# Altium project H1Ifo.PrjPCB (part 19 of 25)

## Sheet IfoEndX3.SchDoc: D1800185
size C; Engineer: Daniel Sigg; DocumentNumber: 7; Revision: 4; SheetNumber: 7; SheetTotal: 8
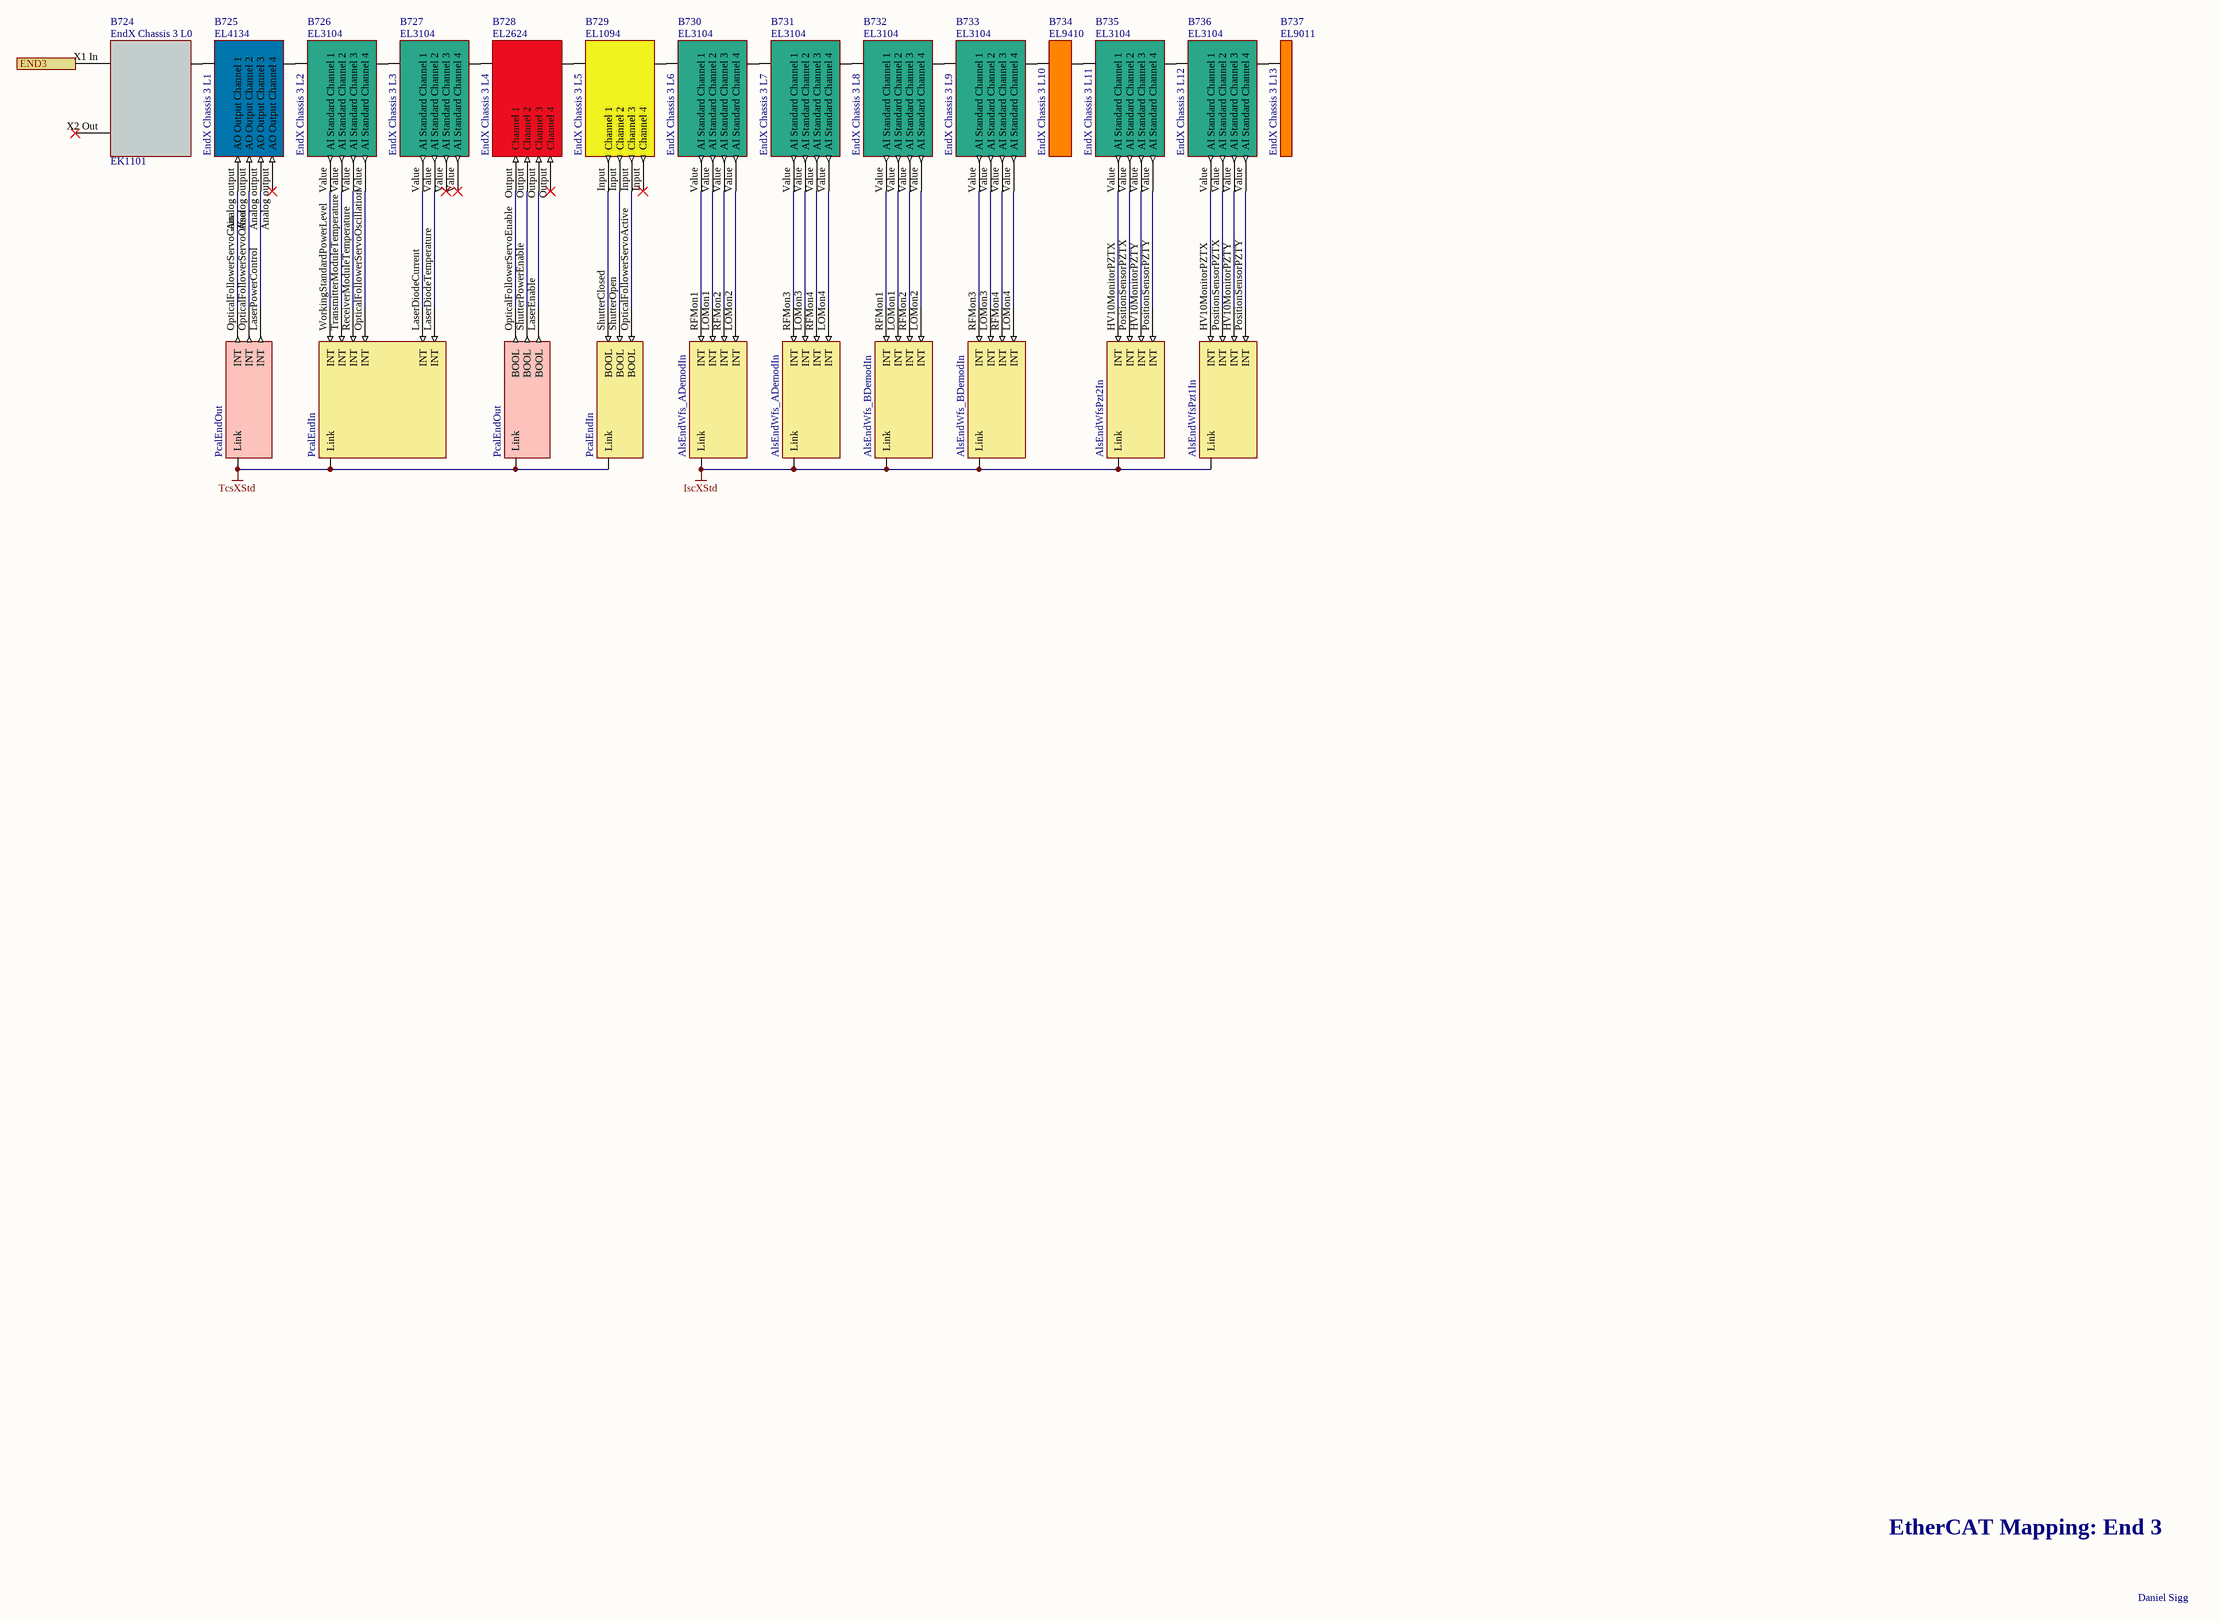
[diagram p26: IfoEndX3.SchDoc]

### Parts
B724  EndX Chassis 3 L0  Part Number: EK1101
B725  EndX Chassis 3 L1  Part Number: EL4134  (mechanical)
B726  EndX Chassis 3 L2  Part Number: EL3104  (mechanical)
B727  EndX Chassis 3 L3  Part Number: EL3104  (mechanical)
B728  EndX Chassis 3 L4  Part Number: EL2624  (mechanical)
B729  EndX Chassis 3 L5  Part Number: EL1094  (mechanical)
B730  EndX Chassis 3 L6  Part Number: EL3104  (mechanical)
B731  EndX Chassis 3 L7  Part Number: EL3104  (mechanical)
B732  EndX Chassis 3 L8  Part Number: EL3104  (mechanical)
B733  EndX Chassis 3 L9  Part Number: EL3104  (mechanical)
B734  EndX Chassis 3 L10  Part Number: EL9410  (mechanical)
B735  EndX Chassis 3 L11  Part Number: EL3104  (mechanical)
B736  EndX Chassis 3 L12  Part Number: EL3104  (mechanical)
B737  EndX Chassis 3 L13  Part Number: EL9011  (mechanical)
V584  PcalEndOut  (parts A,B of 2)  (no BOM)
V585  PcalEndIn  (parts A,B of 2)  (no BOM)
V586  AlsEndWfs_ADemodIn  (parts A,B of 2)  (no BOM)
V594  AlsEndWfs_BDemodIn  (parts A,B of 2)  (no BOM)
V595  AlsEndWfsPzt2In  (no BOM)
V596  AlsEndWfsPzt1In  (no BOM)

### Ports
END3

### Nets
IscXStd: V586.0(Link) V586.1(Link) V594.0(Link) V594.1(Link) V595.0(Link) V596.0(Link)
TcsXStd: V584.0(Link) V584.1(Link) V585.0(Link) V585.1(Link)
NetB710_X2 Out: B724.X1_In(A) ; port END3
NetB724_Ebus: B724.Ebus(B) B725.Ebus(A)
NetB725_Analog output: B725.Analog_output(AO_Output_Channel_1) V584.OpticalFollowerServoGain(INT)
NetB725_Analog output: B725.Analog_output(AO_Output_Channel_2) V584.OpticalFollowerServoOffset(INT)  [a separate net that carries the same name]
NetB725_Analog output: B725.Analog_output(AO_Output_Channel_3) V584.LaserPowerControl(INT)  [a separate net that carries the same name]
NetB725_Ebus: B725.Ebus(B) B726.Ebus(A)
NetB726_Ebus: B726.Ebus(B) B727.Ebus(A)
NetB726_Value: B726.Value(AI_Standard_Channel_1) V585.WorkingStandardPowerLevel(INT)
NetB726_Value: B726.Value(AI_Standard_Channel_2) V585.TransmitterModuleTemperature(INT)  [a separate net that carries the same name]
NetB726_Value: B726.Value(AI_Standard_Channel_3) V585.ReceiverModuleTemperature(INT)  [a separate net that carries the same name]
NetB726_Value: B726.Value(AI_Standard_Channel_4) V585.OpticalFollowerServoOscillation(INT)  [a separate net that carries the same name]
NetB727_Ebus: B727.Ebus(B) B728.Ebus(A)
NetB727_Value: B727.Value(AI_Standard_Channel_1) V585.LaserDiodeCurrent(INT)
NetB727_Value: B727.Value(AI_Standard_Channel_2) V585.LaserDiodeTemperature(INT)  [a separate net that carries the same name]
NetB728_Ebus: B728.Ebus(B) B729.Ebus(A)
NetB728_Output: B728.Output(Channel_1) V584.OpticalFollowerServoEnable(BOOL)
NetB728_Output: B728.Output(Channel_2) V584.ShutterPowerEnable(BOOL)  [a separate net that carries the same name]
NetB728_Output: B728.Output(Channel_3) V584.LaserEnable(BOOL)  [a separate net that carries the same name]
NetB729_Ebus: B729.Ebus(B) B730.Ebus(A)
NetB729_Input: B729.Input(Channel_1) V585.ShutterClosed(BOOL)
NetB729_Input: B729.Input(Channel_2) V585.ShutterOpen(BOOL)  [a separate net that carries the same name]
NetB729_Input: B729.Input(Channel_3) V585.OpticalFollowerServoActive(BOOL)  [a separate net that carries the same name]
NetB730_Ebus: B730.Ebus(B) B731.Ebus(A)
NetB730_Value: B730.Value(AI_Standard_Channel_1) V586.RFMon1(INT)
NetB730_Value: B730.Value(AI_Standard_Channel_2) V586.LOMon1(INT)  [a separate net that carries the same name]
NetB730_Value: B730.Value(AI_Standard_Channel_3) V586.RFMon2(INT)  [a separate net that carries the same name]
NetB730_Value: B730.Value(AI_Standard_Channel_4) V586.LOMon2(INT)  [a separate net that carries the same name]
NetB731_Ebus: B731.Ebus(B) B732.Ebus(A)
NetB731_Value: B731.Value(AI_Standard_Channel_1) V586.RFMon3(INT)
NetB731_Value: B731.Value(AI_Standard_Channel_2) V586.LOMon3(INT)  [a separate net that carries the same name]
NetB731_Value: B731.Value(AI_Standard_Channel_3) V586.RFMon4(INT)  [a separate net that carries the same name]
NetB731_Value: B731.Value(AI_Standard_Channel_4) V586.LOMon4(INT)  [a separate net that carries the same name]
NetB732_Ebus: B732.Ebus(B) B733.Ebus(A)
NetB732_Value: B732.Value(AI_Standard_Channel_1) V594.RFMon1(INT)
NetB732_Value: B732.Value(AI_Standard_Channel_2) V594.LOMon1(INT)  [a separate net that carries the same name]
NetB732_Value: B732.Value(AI_Standard_Channel_3) V594.RFMon2(INT)  [a separate net that carries the same name]
NetB732_Value: B732.Value(AI_Standard_Channel_4) V594.LOMon2(INT)  [a separate net that carries the same name]
NetB733_Ebus: B733.Ebus(B) B734.Ebus(A)
NetB733_Value: B733.Value(AI_Standard_Channel_1) V594.RFMon3(INT)
NetB733_Value: B733.Value(AI_Standard_Channel_2) V594.LOMon3(INT)  [a separate net that carries the same name]
NetB733_Value: B733.Value(AI_Standard_Channel_3) V594.RFMon4(INT)  [a separate net that carries the same name]
NetB733_Value: B733.Value(AI_Standard_Channel_4) V594.LOMon4(INT)  [a separate net that carries the same name]
NetB734_Ebus: B734.Ebus(B) B735.Ebus(A)
NetB735_Ebus: B735.Ebus(B) B736.Ebus(A)
NetB735_Value: B735.Value(AI_Standard_Channel_1) V595.HV10MonitorPZTX(INT)
NetB735_Value: B735.Value(AI_Standard_Channel_2) V595.PositionSensorPZTX(INT)  [a separate net that carries the same name]
NetB735_Value: B735.Value(AI_Standard_Channel_3) V595.HV10MonitorPZTY(INT)  [a separate net that carries the same name]
NetB735_Value: B735.Value(AI_Standard_Channel_4) V595.PositionSensorPZTY(INT)  [a separate net that carries the same name]
NetB736_Ebus: B736.Ebus(B) B737.Ebus(A)
NetB736_Value: B736.Value(AI_Standard_Channel_1) V596.HV10MonitorPZTX(INT)
NetB736_Value: B736.Value(AI_Standard_Channel_2) V596.PositionSensorPZTX(INT)  [a separate net that carries the same name]
NetB736_Value: B736.Value(AI_Standard_Channel_3) V596.HV10MonitorPZTY(INT)  [a separate net that carries the same name]
NetB736_Value: B736.Value(AI_Standard_Channel_4) V596.PositionSensorPZTY(INT)  [a separate net that carries the same name]

Not connected (* = marked no-connect by the designer): B724 X2 Out(C)*

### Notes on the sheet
- EtherCAT Mapping: End 3
- Daniel Sigg

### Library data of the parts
B724 = CouplerEK1101: EtherCAT Coupler; Rail: Left; BoxNextB: JOALOQYJ; BoxPrev: WVQJRASG; PortPrevFull: 1088/C; PortPrevShort: C 'X2 Out'; Fullname: TIID^End X (EtherCAT)^EndX Link L0 (EK1501-0010)^EndX Link L6 (EK1521)^EndX Chassis 3 L0 (EK1101); BoxPorts: Junction; BoxAddr: 1101; Disabled: False
B725 = TerminalEL4134: EtherCAT Terminal EL4134 4-chn Analog Ouput; Rail: Left; BoxNextB: TMDQTKXU; BoxPrev: SGKBFUAI; PortPrevFull: 1101/B; PortPrevShort: B; Fullname: TIID^End X (EtherCAT)^EndX Link L0 (EK1501-0010)^EndX Link L6 (EK1521)^EndX Chassis 3 L0 (EK1101)^EndX Chassis 3 L1 (EL4134); BoxAddr: 1102; Disabled: False
B726 = TerminalEL3104: EtherCAT Terminal EL3104 4-chn Analog Input; Rail: Left; BoxNextB: WWLRMYVT; BoxPrev: JOALOQYJ; PortPrevFull: 1102/B; PortPrevShort: B; Fullname: TIID^End X (EtherCAT)^EndX Link L0 (EK1501-0010)^EndX Link L6 (EK1521)^EndX Chassis 3 L0 (EK1101)^EndX Chassis 3 L2 (EL3104); BoxAddr: 1103; Disabled: False
B727 = TerminalEL3104: EtherCAT Terminal EL3104 4-chn Analog Input; Rail: Left; BoxNextB: ASHOYETR; BoxPrev: TMDQTKXU; PortPrevFull: 1103/B; PortPrevShort: B; Fullname: TIID^End X (EtherCAT)^EndX Link L0 (EK1501-0010)^EndX Link L6 (EK1521)^EndX Chassis 3 L0 (EK1101)^EndX Chassis 3 L3 (EL3104); BoxAddr: 1104; Disabled: False
B728 = TerminalEL2624: EtherCAT Terminal EL2624 4-channel relay output terminal 125 V AC/30 V DC; Rail: Left; BoxNextB: DBIHPMGF; BoxPrev: WWLRMYVT; PortPrevFull: 1104/B; PortPrevShort: B; Fullname: TIID^End X (EtherCAT)^EndX Link L0 (EK1501-0010)^EndX Link L6 (EK1521)^EndX Chassis 3 L0 (EK1101)^EndX Chassis 3 L4 (EL2624); BoxAddr: 1105; Disabled: False
B729 = TerminalEL1094: EtherCAT Terminal EL1094 4-channel digital input terminal 24 V DC, switching to negative potential; Rail: Left; BoxNextB: LUIRLPUG; BoxPrev: ASHOYETR; PortPrevFull: 1105/B; PortPrevShort: B; Fullname: TIID^End X (EtherCAT)^EndX Link L0 (EK1501-0010)^EndX Link L6 (EK1521)^EndX Chassis 3 L0 (EK1101)^EndX Chassis 3 L5 (EL1094); BoxAddr: 1106; Disabled: False
B730 = TerminalEL3104: EtherCAT Terminal EL3104 4-chn Analog Input; Rail: Left; BoxNextB: KBUQGUSU; BoxPrev: DBIHPMGF; PortPrevFull: 1106/B; PortPrevShort: B; Fullname: TIID^End X (EtherCAT)^EndX Link L0 (EK1501-0010)^EndX Link L6 (EK1521)^EndX Chassis 3 L0 (EK1101)^EndX Chassis 3 L6 (EL3104); BoxAddr: 1107; Disabled: False
B731 = TerminalEL3104: EtherCAT Terminal EL3104 4-chn Analog Input; Rail: Left; BoxNextB: TITKQTNS; BoxPrev: LUIRLPUG; PortPrevFull: 1107/B; PortPrevShort: B; Fullname: TIID^End X (EtherCAT)^EndX Link L0 (EK1501-0010)^EndX Link L6 (EK1521)^EndX Chassis 3 L0 (EK1101)^EndX Chassis 3 L7 (EL3104); BoxAddr: 1108; Disabled: False
B732 = TerminalEL3104: EtherCAT Terminal EL3104 4-chn Analog Input; Rail: Left; BoxNextB: LHUKNTVD; BoxPrev: KBUQGUSU; PortPrevFull: 1108/B; PortPrevShort: B; Fullname: TIID^End X (EtherCAT)^EndX Link L0 (EK1501-0010)^EndX Link L6 (EK1521)^EndX Chassis 3 L0 (EK1101)^EndX Chassis 3 L8 (EL3104); BoxAddr: 1109; Disabled: False
B733 = TerminalEL3104: EtherCAT Terminal EL3104 4-chn Analog Input; Rail: Left; BoxNextB: EPCNRMUG; BoxPrev: TITKQTNS; PortPrevFull: 1109/B; PortPrevShort: B; Fullname: TIID^End X (EtherCAT)^EndX Link L0 (EK1501-0010)^EndX Link L6 (EK1521)^EndX Chassis 3 L0 (EK1101)^EndX Chassis 3 L9 (EL3104); BoxAddr: 1110; Disabled: False
B734 = TerminalEL9410: EtherCAT Terminal EL9410 Power; Rail: Left; BoxNextB: BWFIVQXF; BoxPrev: LHUKNTVD; PortPrevFull: 1110/B; PortPrevShort: B; Fullname: TIID^End X (EtherCAT)^EndX Link L0 (EK1501-0010)^EndX Link L6 (EK1521)^EndX Chassis 3 L0 (EK1101)^EndX Chassis 3 L10 (EL9410); BoxAddr: 1111; Disabled: False
B735 = TerminalEL3104: EtherCAT Terminal EL3104 4-chn Analog Input; Rail: Left; BoxNextB: YQQYJIVR; BoxPrev: EPCNRMUG; PortPrevFull: 1111/B; PortPrevShort: B; Fullname: TIID^End X (EtherCAT)^EndX Link L0 (EK1501-0010)^EndX Link L6 (EK1521)^EndX Chassis 3 L0 (EK1101)^EndX Chassis 3 L11 (EL3104); BoxAddr: 1112; Disabled: False
B736 = TerminalEL3104: EtherCAT Terminal EL3104 4-chn Analog Input; Rail: Left; BoxNextB: TREKMSTE; BoxPrev: BWFIVQXF; PortPrevFull: 1112/B; PortPrevShort: B; Fullname: TIID^End X (EtherCAT)^EndX Link L0 (EK1501-0010)^EndX Link L6 (EK1521)^EndX Chassis 3 L0 (EK1101)^EndX Chassis 3 L12 (EL3104); BoxAddr: 1113; Disabled: False
B737 = TerminalEL9011: EtherCAT Terminal EL9011 End; BoxType: TerminalPassive; Rail: Left; BoxPrev: YQQYJIVR; PortPrevShort: B; Fullname: TIID^End X (EtherCAT)^EndX Link L0 (EK1501-0010)^EndX Link L6 (EK1521)^EndX Chassis 3 L0 (EK1101)^EndX Chassis 3 L13 (EL9011); Disabled: False
V584 = Pcal_PcalOutStruct: PcalOutStruct; BoxType: Variable; Instance: H1TcsEndX Instance; PLC: H1TcsEndX; Task: TcsEStd
V585 = Pcal_PcalInStruct: PcalInStruct; BoxType: Variable; Instance: H1TcsEndX Instance; PLC: H1TcsEndX; Task: TcsEStd
V586 V594 = Demodulator_DemodulatorQuadInStruct: DemodulatorQuadInStruct; BoxType: Variable; Instance: H1IscEndX Instance; PLC: H1IscEndX; Task: IscEStd
V595 V596 = PZTMirror_PZTMirrorInStruct: PZTMirrorInStruct; BoxType: Variable; Instance: H1IscEndX Instance; PLC: H1IscEndX; Task: IscEStd

## Sheet IfoEndY0.SchDoc: D1800185
size C; Engineer: Daniel Sigg; DocumentNumber: 4; Revision: 4; SheetNumber: 4; SheetTotal: 8
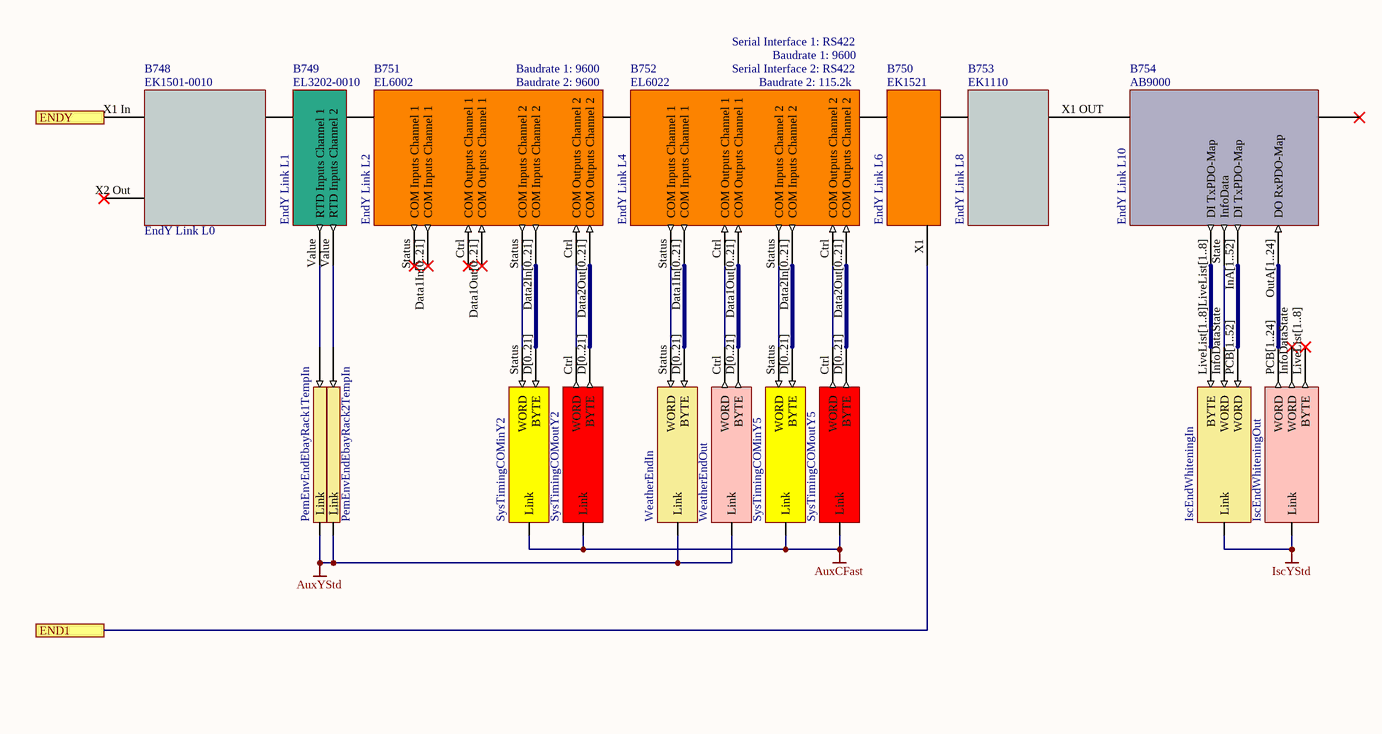
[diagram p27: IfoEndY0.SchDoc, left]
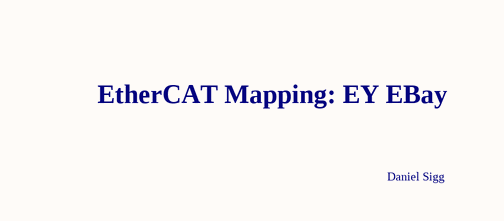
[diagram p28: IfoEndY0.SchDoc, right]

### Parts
B748  EndY Link L0  Part Number: EK1501-0010  (mechanical)
B749  EndY Link L1  Part Number: EL3202-0010  (mechanical)
B750  EndY Link L6  Part Number: EK1521  (mechanical)
B751  EndY Link L2  Part Number: EL6002  Baudrate 1: 9600  (mechanical)
B752  EndY Link L4  Part Number: EL6022  Baudrate 1: 9600  Baudrate 2: 115.2k  Serial Interface 1: RS422  (mechanical)
B753  EndY Link L8  Part Number: EK1110  (mechanical)
B754  EndY Link L10  Part Number: AB9000  (mechanical)
V618  PemEnvEndEbayRack1TempIn  (no BOM)
V619  PemEnvEndEbayRack2TempIn  (no BOM)
V620  IscEndWhiteningIn  (no BOM)
V621  IscEndWhiteningOut  (no BOM)
V622  SysTimingCOMinY2  (no BOM)
V623  SysTimingCOMoutY2  (no BOM)
V624  SysTimingCOMinY5  (no BOM)
V625  SysTimingCOMoutY5  (no BOM)
V847  WeatherEndIn  (no BOM)
V848  WeatherEndOut  (no BOM)

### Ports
END1, ENDY

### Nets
AuxCFast: V622.?1(Link) V623.?1(Link) V624.?1(Link) V625.?1(Link)
AuxYStd: V618.?2(Link) V619.?2(Link) V847.?1(Link) V848.?1(Link)
IscYStd: V620.?1(Link) V621.?1(Link)
NetB611_X1: B750.X1(D) ; port END1
NetB748_Ebus: B748.Ebus(B) B749.Ebus(A)
NetB748_X1 In: B748.X1_In(A) ; port ENDY
NetB749_Ebus: B749.Ebus(B) B751.Ebus(A)
NetB749_Value: B749.Value(RTD_Inputs_Channel_1) V618.?1
NetB749_Value: B749.Value(RTD_Inputs_Channel_2) V619.?1  [a separate net that carries the same name]
NetB750_Ebus: B750.Ebus(A) B752.Ebus(B)
NetB750_Ebus: B750.Ebus(C) B753.Ebus(A)  [a separate net that carries the same name]
NetB751_Ctrl: B751.Ctrl(COM_Outputs_Channel_1) V623.Ctrl(WORD)
NetB751_Data2In[0..21]: B751.Data2In[0..21](COM_Inputs_Channel_2) V622.D[0..21](BYTE)
NetB751_Data2Out[0..21]: B751.Data2Out[0..21](COM_Outputs_Channel_2) V623.D[0..21](BYTE)
NetB751_Ebus: B751.Ebus(B) B752.Ebus(A)
NetB751_Status: B751.Status(COM_Inputs_Channel_1) V622.Status(WORD)
NetB752_Ctrl: B752.Ctrl(COM_Outputs_Channel_1) V848.Ctrl(WORD)
NetB752_Ctrl: B752.Ctrl(COM_Outputs_Channel_2) V625.Ctrl(WORD)  [a separate net that carries the same name]
NetB752_Data1In[0..21]: B752.Data1In[0..21](COM_Inputs_Channel_1) V847.D[0..21](BYTE)
NetB752_Data1Out[0..21]: B752.Data1Out[0..21](COM_Outputs_Channel_1) V848.D[0..21](BYTE)
NetB752_Data2In[0..21]: B752.Data2In[0..21](COM_Inputs_Channel_2) V624.D[0..21](BYTE)
NetB752_Data2Out[0..21]: B752.Data2Out[0..21](COM_Outputs_Channel_2) V625.D[0..21](BYTE)
NetB752_Status: B752.Status(COM_Inputs_Channel_1) V847.Status(WORD)
NetB752_Status: B752.Status(COM_Inputs_Channel_2) V624.Status(WORD)  [a separate net that carries the same name]
NetB753_X1 OUT: B753.X1_OUT(B) B754.?2(A)
NetB754_InA[1..52]: B754.InA[1..52](DI_TxPDO-Map) V620.PCB[1..52](WORD)
NetB754_LiveList[1..8]: B754.LiveList[1..8](DI_TxPDO-Map) V620.LiveList[1..8](BYTE)
NetB754_OutA[1..24]: B754.OutA[1..24](DO_RxPDO-Map) V621.PCB[1..24](WORD)
NetB754_State: B754.State(InfoData) V620.InfoDataState(WORD)

Not connected (* = marked no-connect by the designer): B748 X2 Out(C)*; B751 Data1In[0..21](COM_Inputs_Channel_1)* Data1Out[0..21](COM_Outputs_Channel_1)*; B754 ?1(B)*; V621 InfoDataState(WORD)* LiveList[1..8](BYTE)*

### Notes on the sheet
- EtherCAT Mapping: EY EBay
- Daniel Sigg

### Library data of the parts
B748 = CouplerEK1501: Fiber Coupler; Rail: Left; BoxNextB: TWDJDPST; BoxPrev: SPLHFTMV; PortPrevFull: 1001/B; PortPrevShort: B 'X1'; Fullname: TIID^End Y (EtherCAT)^EndY Link L0 (EK1501-0010); BoxPorts: Junction; BoxAddr: 1002; Disabled: False
B749 = TerminalEL3202-0010: EtherCAT Terminal EL3202-0010 2-chn Temperature Input; Rail: Left; BoxNextB: UBGJKAPH; BoxPrev: JHYOYQCQ; PortPrevFull: 1002/B; PortPrevShort: B; Fullname: TIID^End Y (EtherCAT)^EndY Link L0 (EK1501-0010)^EndY Link L1 (EL3202-0010); BoxAddr: 1003; Disabled: False
B750 = TerminalEK1521: EtherCAT Terminal Fiber; Rail: Left; BoxNextC: YFMTQQBN; BoxNextD: NEQKDDQF; BoxPrev: PMKJUTTD; PortPrevFull: 1005/B; PortPrevShort: B; Fullname: TIID^End Y (EtherCAT)^EndY Link L0 (EK1501-0010)^EndY Link L6 (EK1521); BoxPorts: Junction; BoxAddr: 1006; Disabled: False
B751 = TerminalEL6002: EtherCAT Terminal EL6002 Dual RS232; Rail: Left; BoxNextB: PMKJUTTD; BoxPrev: TWDJDPST; PortPrevFull: 1003/B; PortPrevShort: B; Fullname: TIID^End Y (EtherCAT)^EndY Link L0 (EK1501-0010)^EndY Link L2 (EL6002); BoxAddr: 1004; BoxSubType: 9101; Disabled: False
B752 = TerminalEL6022: EtherCAT Terminal EL6022 Dual RS422; Rail: Left; BoxNextB: CKQXTAKS; BoxPrev: UBGJKAPH; PortPrevFull: 1004/B; PortPrevShort: B; Fullname: TIID^End Y (EtherCAT)^EndY Link L0 (EK1501-0010)^EndY Link L4 (EL6022); BoxAddr: 1005; BoxSubType: 9103; Disabled: False
B753 = CouplerEK1110: EtherCAT Coupler Extension; BoxType: Terminal; Rail: Left; BoxNextB: KTWIWDVY; BoxPrev: CKQXTAKS; PortPrevFull: 1006/C; PortPrevShort: C; Fullname: TIID^End Y (EtherCAT)^EndY Link L0 (EK1501-0010)^EndY Link L8 (EK1110); BoxAddr: 1126; Disabled: False
B754 = Anybus X-gateway 1xBIO: EtherCAT Modbus gateway for 1xBIO; Part Revision: V0000001b_P0000001b_R0001000d; BoxType: Box; BoxPrev: YFMTQQBN; PortPrevFull: 1126/B; PortPrevShort: B 'X1 OUT'; Fullname: TIID^End Y (EtherCAT)^EndY Link L10 (AB9000); BoxAddr: 1127; PDO Inputs: 0x1A01; PDO Outputs: 0x1601; Disabled: False
V618 V619 = VariableInINT: INT; PLC: H1AuxEndY; Task: AuxEStd; Instance: H1AuxEndY Instance
V620 = ISCWhitening_IscWhiteningInStruct: IscWhiteningInStruct; BoxType: Variable; Instance: H1IscEndY Instance; PLC: H1IscEndY; Task: IscEStd
V621 = ISCWhitening_IscWhiteningOutStruct: IscWhiteningOutStruct; BoxType: Variable; Instance: H1IscEndY Instance; PLC: H1IscEndY; Task: IscEStd
V622 V624 = Serial_EL6inData22Bfast: EL6inData22B; PLC: H1AuxCorner; Task: AuxCFast; BoxType: Variable; Instance: H1AuxCorner Instance
V623 V625 = Serial_EL6outData22Bfast: EL6outData22B; PLC: H1AuxCorner; Task: AuxCFast; BoxType: Variable; Instance: H1AuxCorner Instance
V847 = Serial_EL6inData22B: EL6inData22B; PLC: H1AuxEndY; Task: AuxEStd; BoxType: Variable; Instance: H1AuxEndY Instance
V848 = Serial_EL6outData22B: EL6outData22B; PLC: H1AuxEndY; Task: AuxEStd; BoxType: Variable; Instance: H1AuxEndY Instance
